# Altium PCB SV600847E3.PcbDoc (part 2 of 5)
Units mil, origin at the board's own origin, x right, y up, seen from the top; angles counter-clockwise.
Board outline 5404 x 2680 mil, 10 copper layers (Top Layer L1, Gnd-Plane - L2, Signals - L3, Gnd-Plane - L4, Pwr Plane - L5, Signals - L6, Gnd-Plane - L7, Signals - L8, Gnd-Plane - L9, Bottom Layer - L10), stack 57.8 mil thick; 517 components, 320 nets, 1784 pads, 1289 vias.
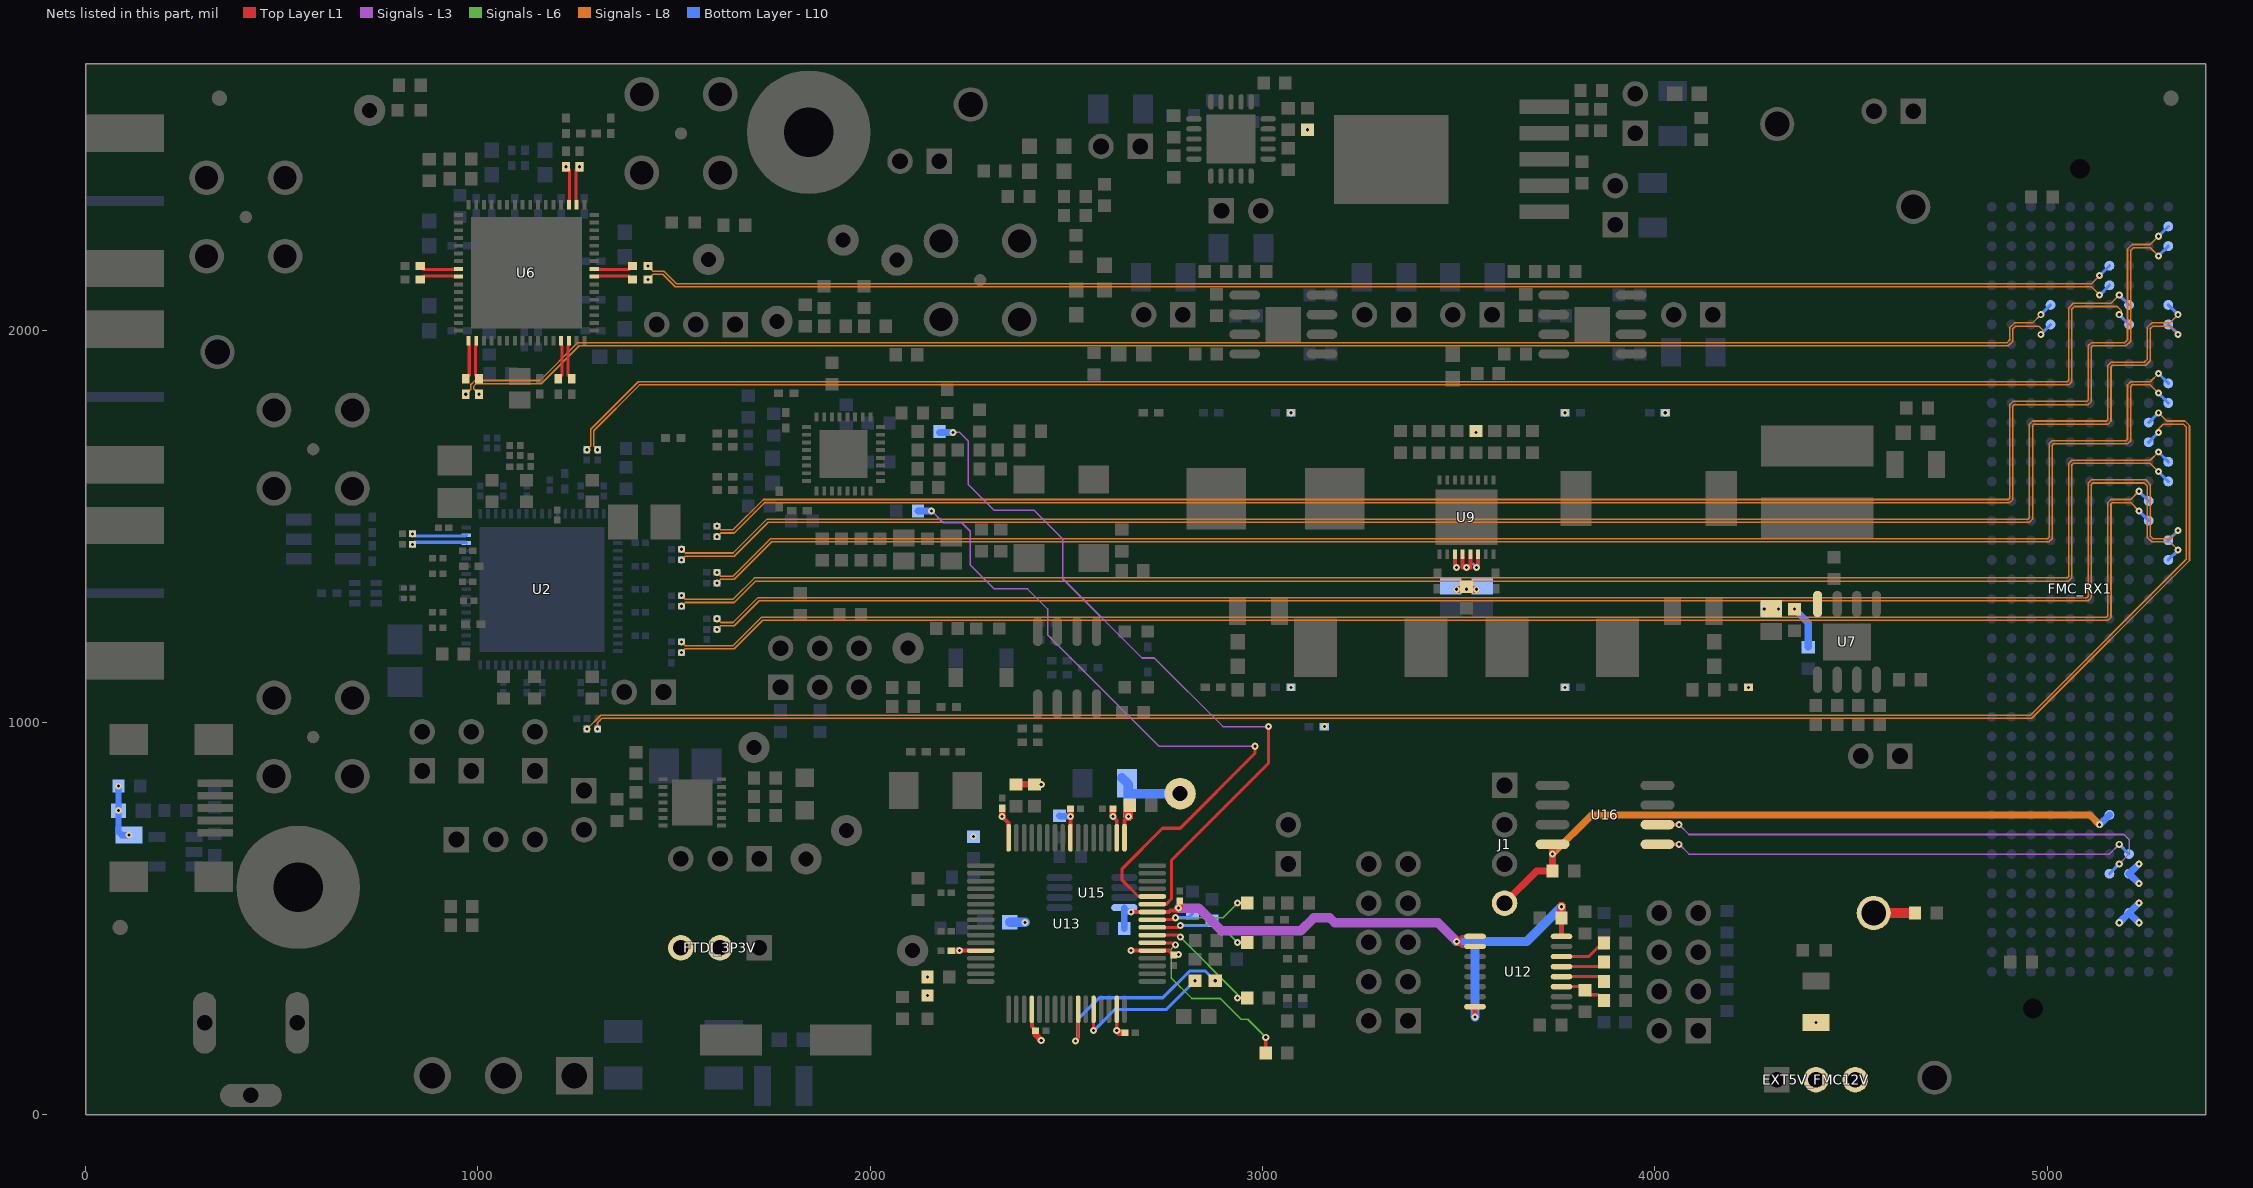
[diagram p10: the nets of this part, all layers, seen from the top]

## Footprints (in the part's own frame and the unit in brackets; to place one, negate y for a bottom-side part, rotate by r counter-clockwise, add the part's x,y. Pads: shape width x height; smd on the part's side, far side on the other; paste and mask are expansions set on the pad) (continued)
Keystone5011 [mil] "Keystone Multipurpose loops"
  round 87 hole 63: 1(0,0)
  silkscreen extent -70,-70 70,70, body extent -63,-63 63,62, height 319
Keystone_1902C [mil] "Hex Standoff, 4-40 threaded, nylon"
  round 1 on Mech4: 0(0,0)
  body extent -145,-126 146,126, height 501
Label_650x200 [mil] "Thermal Transfer Label"
  silkscreen extent -325,-100 325,100, body extent -326,-101 326,101, height 1
LED_LTST-C170 [mm] "LITE-ON"
  rect 1.2x1.2 smd: 1(-1.05,0) 2(1.05,0)
  silkscreen extent -1.6,-1.1 3,1.1, body extent -1.05,-0.67 1.05,0.67, height 1.1
LED_LTST-C190 [mm] "Lite-On"
  rect 0.8x0.8 smd: 1(-0.75,0) 2(0.75,0)
  silkscreen extent -1.1,-0.8 1.8,0.8, body extent -0.85,-0.45 0.85,0.45, height 0.9
LQFP64_N [mm] "Thin QFP, 64-Leads, Body 10x10mm, Pitch 0.5mm, IPC Medium Density"
  oval 1.8x0.3 smd mask+0.049: 1(-5.55,3.75) 2(-5.55,3.25) 3(-5.55,2.75) 4(-5.55,2.25) 5(-5.55,1.75) 6(-5.55,1.25) 7(-5.55,0.75) 8(-5.55,0.25) 9(-5.55,-0.25) 10(-5.55,-0.75) 11(-5.55,-1.25) 12(-5.55,-1.75) 13(-5.55,-2.25) 14(-5.55,-2.75) 15(-5.55,-3.25) 16(-5.55,-3.75) 33(5.55,-3.75) 34(5.55,-3.25) 35(5.55,-2.75) 36(5.55,-2.25) 37(5.55,-1.75) 38(5.55,-1.25) 39(5.55,-0.75) 40(5.55,-0.25) 41(5.55,0.25) 42(5.55,0.75) 43(5.55,1.25) 44(5.55,1.75) 45(5.55,2.25) 46(5.55,2.75) 47(5.55,3.25) 48(5.55,3.75)
  oval 0.3x1.8 smd mask+0.049: 17(-3.75,-5.55) 18(-3.25,-5.55) 19(-2.75,-5.55) 20(-2.25,-5.55) 21(-1.75,-5.55) 22(-1.25,-5.55) 23(-0.75,-5.55) 24(-0.25,-5.55) 25(0.25,-5.55) 26(0.75,-5.55) 27(1.25,-5.55) 28(1.75,-5.55) 29(2.25,-5.55) 30(2.75,-5.55) 31(3.25,-5.55) 32(3.75,-5.55) 49(3.75,5.55) 50(3.25,5.55) 51(2.75,5.55) 52(2.25,5.55) 53(1.75,5.55) 54(1.25,5.55) 55(0.75,5.55) 56(0.25,5.55) 57(-0.25,5.55) 58(-0.75,5.55) 59(-1.25,5.55) 60(-1.75,5.55) 61(-2.25,5.55) 62(-2.75,5.55) 63(-3.25,5.55) 64(-3.75,5.55)
  silkscreen extent -5.67,-4.25 4.25,4.57, body extent -5,-5 5,5, height 1.6
M08A_L [mm] "SOIC, 8-Leads, Body 4.9x3.9mm, Pitch 1.27mm, IPC High Density"
  oval 1.9x0.6 smd: 1(-2.35,1.905) 2(-2.35,0.635) 3(-2.35,-0.635) 4(-2.35,-1.905) 5(2.35,-1.905) 6(2.35,-0.635) 7(2.35,0.635) 8(2.35,1.905)
  silkscreen extent -2.47,-2.5 1,2.88, body extent -2,-2.5 2,2.5, height 1.75
Mini-Circuits-DB1627 [mm] "Mini-Circuits DB1627 Footprint"
  rect 0.76x1.65 smd: 1(-1.27,1.59) 2(0,1.59) 3(1.27,1.59) 4(1.27,-1.59) 5(0,-1.59) 6(-1.27,-1.59)
  silkscreen extent -3.01,-2.03 1.91,2.03, body extent -1.91,-2.03 1.91,2.03, height 4.07
MRA08A_N [mm] "SOIC, 8-Leads, Body 4.9x3.9mm, Pitch 1.27mm, Exposed Pad, IPC Medium Density"
  oval 2x0.6 smd: 1(-2.5,1.905) 2(-2.5,0.635) 3(-2.5,-0.635) 4(-2.5,-1.905) 5(2.5,-1.905) 6(2.5,-0.635) 7(2.5,0.635) 8(2.5,1.905)
  rect 2.29x2.29 smd: 9(0,0)
  silkscreen extent -2.63,-2.5 1.1,2.88, body extent -2,-2.5 2,2.5, height 1.68
MSOP-MS8_N [mm] "TSOP, 8-Leads, Body 3x3mm, Pitch 0.65mm, IPC Medium Density"
  oval 1.7x0.45 smd mask+0.049: 1(-2.1,0.975) 2(-2.1,0.325) 3(-2.1,-0.325) 4(-2.1,-0.975) 5(2.1,-0.975) 6(2.1,-0.325) 7(2.1,0.325) 8(2.1,0.975)
  silkscreen extent -2.22,-1.55 0.85,1.87, body extent -1.6,-1.6 1.6,1.6, height 1.1
MSS1038 [mil]
  rect 80x140 smd: 1(-185,0) 2(185,0)
  silkscreen extent -216,-208 215,208, body extent -203,-201 203,201, height 158
NKD0064A [mm] "QFN, 64-Leads, Body 9x9mm, Pitch 0.5mm"
  rect 0.6x0.25 smd mask+0.051: 1(-4.4,3.75) 2(-4.4,3.25) 3(-4.4,2.75) 4(-4.4,2.25) 5(-4.4,1.75) 6(-4.4,1.25) 7(-4.4,0.75) 8(-4.4,0.25) 9(-4.4,-0.25) 10(-4.4,-0.75) 11(-4.4,-1.25) 12(-4.4,-1.75) 13(-4.4,-2.25) 14(-4.4,-2.75) 15(-4.4,-3.25) 16(-4.4,-3.75) 33(4.4,-3.75) 34(4.4,-3.25) 35(4.4,-2.75) 36(4.4,-2.25) 37(4.4,-1.75) 38(4.4,-1.25) 39(4.4,-0.75) 40(4.4,-0.25) 41(4.4,0.25) 42(4.4,0.75) 43(4.4,1.25) 44(4.4,1.75) 45(4.4,2.25) 46(4.4,2.75) 47(4.4,3.25) 48(4.4,3.75)
  rect 0.25x0.6 smd mask+0.051: 17(-3.75,-4.4) 18(-3.25,-4.4) 19(-2.75,-4.4) 20(-2.25,-4.4) 21(-1.75,-4.4) 22(-1.25,-4.4) 23(-0.75,-4.4) 24(-0.25,-4.4) 25(0.25,-4.4) 26(0.75,-4.4) 27(1.25,-4.4) 28(1.75,-4.4) 29(2.25,-4.4) 30(2.75,-4.4) 31(3.25,-4.4) 32(3.75,-4.4) 49(3.75,4.4) 50(3.25,4.4) 51(2.75,4.4) 52(2.25,4.4) 53(1.75,4.4) 54(1.25,4.4) 55(0.75,4.4) 56(0.25,4.4) 57(-0.25,4.4) 58(-0.75,4.4) 59(-1.25,4.4) 60(-1.75,4.4) 61(-2.25,4.4) 62(-2.75,4.4) 63(-3.25,4.4) 64(-3.75,4.4)
  rect 7.2x7.2 smd paste-3.6 mask+0.051: 65(0,0)
  silkscreen extent -5.52,-4.85 4.85,4.85, body extent -4.55,-4.55 4.55,4.55, height 0.8
"NY PMS 440 0025 PH"#1 [mm] "4-40 nylon screw and mounting hole"
  round 8 / inner round 4.216 / far side round 8 hole 3.2 mask+0.037: 1(0,0)
  body extent -3.3,-3.3 3.3,3.3, height 2.69
"NY PMS 440 0025 PH"#2 [mm] "4-40 nylon screw and mounting hole"
  round 8 / inner round 4.216 / far side round 8 hole 3.2: 1(0,0)
  body extent -3.3,-3.3 3.3,3.3, height 2.69
OSC_CWX [mm] "CONNOR WINFIELD"
  rect 2x1.8 smd: 1(-2.1,2.54) 2(-2.1,-2.54) 3(2.1,-2.54) 4(2.1,2.54)
  silkscreen extent -2.7,-3.7 2.7,4.55, body extent -2.65,-3.65 2.65,3.65, height 1.31
PBC03SAAN [mm] "Sullins 100mil, 1x3, 230 mil above insulator"
  rect 1.65x1.65 hole 1.016: 1(-2.54,0)
  round 1.65 hole 1.016: 2(0,0) 3(2.54,0)
  silkscreen extent -3.81,-1.27 3.81,1.27, body extent -3.81,-1.27 3.81,1.27, height 8.38
PW0016A_L [mm] "TSOP, 16-Leads, Body 5x4.4mm, Pitch 0.65mm, IPC High Density"
  oval 1.4x0.35 smd: 1(-2.8,2.275) 2(-2.8,1.625) 3(-2.8,0.975) 4(-2.8,0.325) 5(-2.8,-0.325) 6(-2.8,-0.975) 7(-2.8,-1.625) 8(-2.8,-2.275) 9(2.8,-2.275) 10(2.8,-1.625) 11(2.8,-0.975) 12(2.8,-0.325) 13(2.8,0.325) 14(2.8,0.975) 15(2.8,1.625) 16(2.8,2.275)
  silkscreen extent -2.92,-2.55 1.7,3.12, body extent -2.25,-2.55 2.25,2.55, height 1.2
RGW0020A [mm] "QFN, 20-Leads, Body 5x5mm, Pitch 0.65mm, Thermal Pad 3.15x3.15mm, TI Recommended"
  oval 1x0.35 smd paste-0.025 mask+0.07: 1(-2.4,1.3) 2(-2.4,0.65) 3(-2.4,0) 4(-2.4,-0.65) 5(-2.4,-1.3) 11(2.4,-1.3) 12(2.4,-0.65) 13(2.4,0) 14(2.4,0.65) 15(2.4,1.3)
  oval 0.35x1 smd paste-0.025 mask+0.07: 6(-1.3,-2.4) 7(-0.65,-2.4) 8(0,-2.4) 9(0.65,-2.4) 10(1.3,-2.4) 16(1.3,2.4) 17(0.65,2.4) 18(0,2.4) 19(-0.65,2.4) 20(-1.3,2.4)
  rect 3.15x3.15 smd paste-1.575 mask+0.07: 21(0,0)
  silkscreen extent -3.5,-2.73 2.73,2.73, body extent -2.58,-2.57 2.57,2.58, height 1
RLY0068A [mm] "QFN, 68-Leads, Body 10x10mm, Pitch 0.5mm"
  rect 0.6x0.25 smd mask+0.051: 1(-4.9,4) 2(-4.9,3.5) 3(-4.9,3) 4(-4.9,2.5) 5(-4.9,2) 6(-4.9,1.5) 7(-4.9,1) 8(-4.9,0.5) 9(-4.9,0) 10(-4.9,-0.5) 11(-4.9,-1) 12(-4.9,-1.5) 13(-4.9,-2) 14(-4.9,-2.5) 15(-4.9,-3) 16(-4.9,-3.5) 17(-4.9,-4) 35(4.9,-4) 36(4.9,-3.5) 37(4.9,-3) 38(4.9,-2.5) 39(4.9,-2) 40(4.9,-1.5) 41(4.9,-1) 42(4.9,-0.5) 43(4.9,0) 44(4.9,0.5) 45(4.9,1) 46(4.9,1.5) 47(4.9,2) 48(4.9,2.5) 49(4.9,3) 50(4.9,3.5) 51(4.9,4)
  rect 0.25x0.6 smd mask+0.051: 18(-4,-4.9) 19(-3.5,-4.9) 20(-3,-4.9) 21(-2.5,-4.9) 22(-2,-4.9) 23(-1.5,-4.9) 24(-1,-4.9) 25(-0.5,-4.9) 26(0,-4.9) 27(0.5,-4.9) 28(1,-4.9) 29(1.5,-4.9) 30(2,-4.9) 31(2.5,-4.9) 32(3,-4.9) 33(3.5,-4.9) 34(4,-4.9) 52(4,4.9) 53(3.5,4.9) 54(3,4.9) 55(2.5,4.9) 56(2,4.9) 57(1.5,4.9) 58(1,4.9) 59(0.5,4.9) 60(0,4.9) 61(-0.5,4.9) 62(-1,4.9) 63(-1.5,4.9) 64(-2,4.9) 65(-2.5,4.9) 66(-3,4.9) 67(-3.5,4.9) 68(-4,4.9)
  rect 8.1x8.1 smd paste-4.05 mask+0.051: 69(0,0)
  silkscreen extent -5.87,-5.2 5.2,5.2, body extent -5.05,-5.05 5.05,5.05, height 1.01
RTV0032A [mm] "QFN, 32-Leads, Body 5x5mm, Pitch 0.5mm"
  rect 0.6x0.25 smd mask+0.051: 1(-2.4,1.75) 2(-2.4,1.25) 3(-2.4,0.75) 4(-2.4,0.25) 5(-2.4,-0.25) 6(-2.4,-0.75) 7(-2.4,-1.25) 8(-2.4,-1.75) 17(2.4,-1.75) 18(2.4,-1.25) 19(2.4,-0.75) 20(2.4,-0.25) 21(2.4,0.25) 22(2.4,0.75) 23(2.4,1.25) 24(2.4,1.75)
  rect 0.25x0.6 smd mask+0.051: 9(-1.75,-2.4) 10(-1.25,-2.4) 11(-0.75,-2.4) 12(-0.25,-2.4) 13(0.25,-2.4) 14(0.75,-2.4) 15(1.25,-2.4) 16(1.75,-2.4) 25(1.75,2.4) 26(1.25,2.4) 27(0.75,2.4) 28(0.25,2.4) 29(-0.25,2.4) 30(-0.75,2.4) 31(-1.25,2.4) 32(-1.75,2.4)
  rect 3.1x3.1 smd paste-1.55 mask+0.051: 33(0,0)
  silkscreen extent -3.52,-2.85 2.85,2.85, body extent -2.55,-2.55 2.55,2.55, height 0.8
SDA14B [mm] "SON, 14-Leads, Body 4x4mm, Pitch 0.5mm, NSC Recommended"
  rect 0.6x0.25 smd paste-0.125 mask+0.051: 1(-1.9,1.5) 2(-1.9,1) 3(-1.9,0.5) 4(-1.9,0) 5(-1.9,-0.5) 6(-1.9,-1) 7(-1.9,-1.5) 8(1.9,-1.5) 9(1.9,-1) 10(1.9,-0.5) 11(1.9,0) 12(1.9,0.5) 13(1.9,1) 14(1.9,1.5)
  rect 2.6x3 smd paste-1.3 mask+0.051: 15(0,0)
  silkscreen extent -2.82,-2.2 2.35,2.87, body extent -2.05,-2.05 2.05,2.05, height 0.8
SDA16A [mm] "SON, 16-Leads, Body 5x5mm, Pitch 0.5mm, NSC Recommended"
  rect 0.6x0.25 smd paste-0.125 mask+0.051: 1(-2.4,1.75) 2(-2.4,1.25) 3(-2.4,0.75) 4(-2.4,0.25) 5(-2.4,-0.25) 6(-2.4,-0.75) 7(-2.4,-1.25) 8(-2.4,-1.75) 9(2.4,-1.75) 10(2.4,-1.25) 11(2.4,-0.75) 12(2.4,-0.25) 13(2.4,0.25) 14(2.4,0.75) 15(2.4,1.25) 16(2.4,1.75)
  rect 3.6x4 smd paste-1.8 mask+0.051: 17(0,0)
  silkscreen extent -2.85,-2.7 2.85,3.53, body extent -2.55,-2.55 2.55,2.55, height 0.8
SM_RADIAL_F [mm] "8 x 10.2mm:  Panasonic F"
  rect 4x2 smd: 1(-3.55,0) 2(3.55,0)
  silkscreen extent -4.25,-4.25 4.25,4.25, body extent -4.26,-4.26 4.26,4.26, height 10.5
SMC [mil] "Molded Diode, 2-Leads, Body 6.9x5.8mm, IPC Medium Density, based on OnSemi component dimensions and land patterns"
  rect 110x150 smd: 1(-140.49,0) 2(140.49,0)
  silkscreen extent -221,-124 189,124, body extent -156,-116 156,116, height 91
SNT-100-BK-G [mil] "Samtec STEP model"
  round 1 on Mech3: 0(0,0)
  body extent -100,-50 100,50, height 344
SOD-123 [mm] "On Semi recommended land pattern"
  rect 0.915x1.22 smd: 1(-1.637,0) 2(1.637,0)
  silkscreen extent -2.74,-1.17 2.03,1.17, body extent -1.93,-0.9 1.93,0.9, height 1.35
SOIJ-SM8_N [mm] "SOP, 8-Leads, Body 5.2x5.2mm, Pitch 1.27mm, IPC Medium Density"
  oval 2.2x0.6 smd: 1(-3.4,1.905) 2(-3.4,0.635) 3(-3.4,-0.635) 4(-3.4,-1.905) 5(3.4,-1.905) 6(3.4,-0.635) 7(3.4,0.635) 8(3.4,1.905)
  silkscreen extent -3.52,-2.75 1.9,2.88, body extent -2.73,-2.75 2.73,2.75, height 2.04
"SW_ L101011MS02Q" [mm] "SWITCH SLIDE sPST 4A PCB"
  rect 2.416x2.416 hole 1.65: 1(2.855,4.6)
  round 2.416 hole 1.65: 2(2.855,0) 3(2.855,-4.6)
  silkscreen extent -5.4,-9.55 5.4,9.55, body extent -5.39,-9.55 5.39,9.55, height 14.18
TESTPOINT [mil]
  round 80 hole 37.99: 1(0,0)
TI_Symbol_Overlay_Small [mil]
  silkscreen extent -90,-88 91,88
TJ5A_N [mm] "D2-PAK, 6-Leads, Body 9.9x10.2mm, Pitch 1.7mm, Lead Span 14mm, IPC Medium Density"
  rect 3.2x0.95 smd: 1(-6,3.4) 2(-6,1.7) 3(-6,0) 4(-6,-1.7) 5(-6,-3.4)
  rect 7.4x5.75 smd: 6(3.9,0)
  silkscreen extent -6.12,-5.2 -0.2,5.2, body extent -1.95,-5.2 8.15,5.2, height 2.1
TSW-102-07-G-S [mm] "Samtec 100mil, 1x2, 230 mil above insulator"
  rect 1.65x1.65 hole 1.016 mask+0: 1(-1.27,0)
  round 1.65 hole 1.016 mask+0: 2(1.27,0)
  silkscreen extent -3.56,-1.27 2.54,1.27, body extent -2.54,-1.27 2.54,1.27, height 8.38
TSW-103-07-G-D [mm] "Samtec 100mil, 2x3, 230 mil above insulator"
  rect 1.65x1.65 hole 1.016 mask+0: 1(-2.54,-1.27)
  round 1.65 hole 1.016 mask+0: 2(-2.54,1.27) 3(0,-1.27) 4(0,1.27) 5(2.54,-1.27) 6(2.54,1.27)
  silkscreen extent -4.83,-2.54 3.81,2.54, body extent -3.81,-2.54 3.81,2.54, height 8.38
TSW-103-07-G-S [mm] "Samtec 100mil, 1x3, 230 mil above insulator"
  rect 1.65x1.65 hole 1.016 mask+0: 1(-2.54,0)
  round 1.65 hole 1.016 mask+0: 2(0,0) 3(2.54,0)
  silkscreen extent -4.84,-1.27 3.81,1.27, body extent -3.81,-1.27 3.81,1.27, height 8.38
TSW-104-07-G-D [mm] "Samtec 100mil, 2x4, 230 mil above insulator"
  rect 1.65x1.65 hole 1.016 mask+0: 1(-3.81,-1.27)
  round 1.65 hole 1.016 mask+0: 2(-3.81,1.27) 3(-1.27,-1.27) 4(-1.27,1.27) 5(1.27,-1.27) 6(1.27,1.27) 7(3.81,-1.27) 8(3.81,1.27)
  silkscreen extent -6.1,-2.54 5.08,2.54, body extent -5.08,-2.54 5.08,2.54, height 8.38
TSW-104-07-G-S [mm] "Samtec 100mil, 1x4, 230 mil above insulator"
  rect 1.65x1.65 hole 1.016 mask+0: 1(-3.81,0)
  round 1.65 hole 1.016 mask+0: 2(-1.27,0) 3(1.27,0) 4(3.81,0)
  silkscreen extent -6.1,-1.27 5.08,1.27, body extent -5.08,-1.27 5.08,1.27, height 8.38
WE-HC6 [mm] "Wurth Electronik recommended land pattern"
  rect 3.85x4 smd: 1(-3.825,0) 2(3.825,0)
  silkscreen extent -6.2,-6.2 6.2,6.2, body extent -5.77,-5.37 5.75,5.35, height 5
XTAL_ABM3 [mm] "Abracon recommended land pattern 12.28.10"
  rect 1.9x2.4 smd: 1(-2.05,0) 2(2.05,0)
  silkscreen extent -2.67,-1.78 2.67,1.78, body extent -2.6,-1.7 2.6,1.7, height 1.3

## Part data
1P8USB 3P3USB FLout LD1 LD2 MUX TCRIT1 TCRIT2 TCRIT3 TP_LD Vtune: "TEST POINT.  No entry in BOM."
1V2ADC_INT 1V2ADC_LDO 1V9ADC 1V9INT J3 "KC705 JTAG" LMK_INT LMK_LDO LMX_INT LMX_LDO PG_RX1 Tdiode VA12 VA19 Vbg Vcmo VD12: "Header, TH, 100mil, 2x1, Gold plated, 230 mil above insulator"
3P3RX GND GND1 GND2 GND3 VADJ_RX: "Test Point, TH, Multipurpose, Black"
5VDC: "Connector, DC Jack 2.1X5.5 mm, TH"
12V LD MUXout Status1 Status2 USB_PWR: "LED, Green, SMD"
C1 C3 C5 C6: "CAP, CERM, 100pF, 16V, +/-10%, X7R, 0201"
C2 C8 C11 C215 C216 C217 C218 C219 C220 C221 C222 C223 C224 C225 C226 C227: "CAP, CERM, 0.1uF, 10V, +/-10%, X7R, 0402"
C4: "CAP, CERM, 10pF, 50V, +/-5%, C0G/NP0, 0402"
C7 C9 C10 C12 C13 C14 C15 C17 C20 C21 C22 C23 C26 C28 C29 C31 C41 C42 C43 C44 C45 C46 C47 C51 C52 C53 C54 C55 C56 C57 C58 C62 C63 C64 C65 C66 C67 C68 C69 C70 C71 C118 C119 C131 C132 C133 C134 C136 C140 C142 C214: library part Capacitor, "CAP, CERM, 0.1uF, 6.3V, X5R, 10%, 0201"
C16: "CAP, CERM, 4.7uF, 6.3V, +/-20%, X5R, 0402"
C18 C19 C103 C104 C105 C106 C107 C109 C110 C111 C112 C113 C114 C120 C121 C123 C124 C206 C207 C208 C209: "CAP, CERM, 0.1uF, 10V, +/-10%, X5R, 0402"
C24 C74 C79 C115 C210: "CAP, CERM, 0.1uF, 16V, +/-5%, X7R, 0603"
C25 C34 C38 C76 C77 C78 C88 C89 C91 C93 C94 C98 C99: "CAP, CERM, 100pF, 50V, +/-5%, C0G/NP0, 0603"
C27 C48 C59 C72: "CAP, TANT, 10uF, 10V, +/-20%, 2.5 ohm, 3528-21 SMD"
C30 C36: "CAP, CERM, 0.22uF, 6.3V, +/-20%, X5R, 0201"
C32 C33 C35 C37: "CAP, CERM, 4700pF, 10V, +/-10%, X5R, 0201"
C39 C40 C49 C50 C60 C61 C125 C143 C205: "CAP, CERM, 1uF, 10V, +/-10%, X5R, 0603"
C73: "CAP, CERM, 1uF, 16V, +/-10%, X7R, 0603"
C75 C95 C96 C97 C100 C101 C213: "CAP, CERM, 100pF, 25V, +/-5%, C0G/NP0, 0402"
C80 C82 C139 C141 C150 C152 C158 C163 C165 C166 C171 C172 C186 C188 C190 C195 C196 C197 C200 C202 C203 C204: "CAP, CERM, 10uF, 10V, +/-10%, C0G/NP0, 0603"
C81 C83: "CAP, CERM, 22uF, 10V, +/-20%, X5R, 0805"
C84: "CAP, CERM, 2.2uF, 10V, +/-10%, X5R, 0603"
C85: "CAP, CERM, 0.01uF, 100V, +/-10%, X7R, 0603"
C86: "CAP, CERM, 1500pF, 50V, +/-5%, C0G/NP0, 0603"
C87: "CAP, CERM, 0.1uF, 50V, +/-10%, X7R, 0603"
C90: "CAP, CERM, 0.022uF, 25V, +/-10%, X7R, 0603"
C92: "CAP, CERM, 680pF, 100V, +/-5%, X7R, 0603"
C102: "CAP, CERM, 0.01uF, 16V, +/-10%, X7R, 0402"
C108 C155 C201 C211: "CAP, CERM, 1uF, 16V, +/-10%, X5R, 0603"
C116 C126 C129 C130 C144 C147 C148 C151 C153 C159 C164 C167 C176 C177 C185 C189 C191 C198 C199: "CAP, CERM, 0.1uF, 25V, +/-5%, X7R, 0603"
C117 C149: "CAP, CERM, 330pF, 50V, +/-5%, C0G/NP0, 0603"
C122: "CAP, CERM, 10uF, 10V, +/-10%, X5R, 0805"
C127 C160: "CAP, CERM, 4.7uF, 10V, +/-10%, X5R, 0603"
C128 C161: "CAP, CERM, 0.01uF, 100V, +/-20%, X7R, 0603"
C135 C137: "CAP, CERM, 18pF, 50V, +/-5%, C0G/NP0, 0402"
C138 C212: "CAP, CERM, 100uF, 6.3V, +/-20%, X5R, 1206"
C145 C146 C173 C184: "CAP, CERM, 10uF, 16V, +/-10%, X5R, 0805"
C154: "CAP, CERM, 10pF, 50V, +/-5%, C0G/NP0, 0603"
C156 C157: "CAP, CERM, 47uF, 6.3V, +/-20%, X5R, 1206"
C162: "CAP, CERM, 3300pF, 25V, +/-10%, X7R, 0603"
C168: "CAP, CERM, 0.22uF, 16V, +/-10%, X7R, 0603"
C169 C170: "CAP, CERM, 0.1uF, 6.3V, +/-10%, X5R, 0402"
C174 C175: "CAP, CERM, 0.027uF, 16V, +/-10%, X7R, 0603"
C178 C179: "CAP, CERM, 0.039uF, 25V, +/-10%, X7R, 0603"
C180 C181 C182 C183: "CAP, CERM, 22uF, 10V, +/-20%, X5R, 1206"
C187: "CAP, CERM, 560pF, 50V, +/-5%, C0G/NP0, 0603"
C192: "CAP, CERM, 4700pF, 16V, +/-10%, X7R, 0603"
C193: "CAP, AL, 100uF, 25V, +/-20%, 0.3 ohm, SMD"
C194: "CAP, CERM, 10uF, 25V, +/-10%, X6S, 1210"
C228 C229: library part GRM155R71A104KA01D, "CAP CER 0.5PF 50V NP0 0402"
D2 D4: "Diode, Ultrafast, 100V, 0.15A, SOD-123"
D11 D12: "Diode, Schottky, 40V, 5A, SMC"
DEVCLK LMKCLK OSCin VIN+ VIN-: "Connector, SMA,Vertical, Thru hole w/SMT center pin"
EXT5V_FMC12V: "Header, TH, 100mil, 1x3, Gold plated, 230 mil above insulator"
FID1 FID2 FID3: "Fiducial mark.  There is nothing to buy or mount."
FMC_RX1: "Connector, Receptacle, 400-Pos (40x10), 50x50-mil Pitch, SMT"
FTDI_3P3V OR RSV "Ts ADD1": "Header, TH, 100mil, 3x1, Gold plated, 230 mil above insulator"
H3 H4: library part 1902C, "Standoff, Hex, 0.25\"L #4-40 Nylon"
H5 H6: "Machine Screw, Round, #4-40 x 1/4, Nylon, Philips panhead"
J1: "Header, TH, 100mil, 4x1, Gold plated, 230 mil above insulator"
L1 L7 L14 L20 L24 L25: "3A Ferrite Bead, 120 ohm @ 100MHz, SMD"
L2 L3 L4 L5 L19 L21 L22 L23: "1.5A Ferrite Bead, 330 ohm @ 100MHz, SMD"
L6 L9 L10 L13 L15 L16 L17 L18 L26: "6A Ferrite Bead, 26 ohm @ 100MHz, SMD"
L8: "Inductor, Shielded Drum Core, Ferrite, 3uH, 3A, 0.024 ohm, SMD"
L11: "Inductor, Shielded Drum Core, Ferrite, 7uH, 4.35A, 0.03 ohm, SMD"
L12: "Inductor, Shielded Drum Core, Superflux, 5.5uH, 10A, 0.0112 ohm, SMD"
LBL1: library part THT-14-423-10, "Thermal Transfer Printable Labels, 0.650\" W x 0.200\" H - 10,000 per roll"
LF1: "CAP, CERM, 3900pF, 25V, +/-5%, C0G/NP0, 0603"
LF2: "CAP, CERM, 47pF, 50V, +/-5%, C0G/NP0, 0603"
LF3: "RES, 619 ohm, 1%, 0.1W, 0603"
LF7: "Coupled inductor, 5A, 0.01 ohm, SMD"
Logo1: library part ESD_Susceptible, "ESD Susceptible Symbol"
Logo2: library part TI_Logo, "Texas Instrument Corporate Signature"
NCO: "Header, TH, 100mil, 3x2, Gold plated, 230 mil above insulator"
OR_T0 OR_T1: "LED, Orange, SMD"
R1: "RES, 8.06k ohm, 1%, 0.063W, 0402"
R2 R10: "RES, 1.2k ohm, 5%, 0.063W, 0402"
R3 R11: "RES, 1.0Meg ohm, 5%, 0.063W, 0402"
R4 R5 R6 R14 R15 R16 R105 R106 R107 R123 R130 R131: "RES, 10.0k ohm, 1%, 0.1W, 0603"
R7 R8 R9 R18 R19 R20 R21 R22 R23: library part "Res 0201 placeholder", "RES 0.0 OHM 1/20W 0201 SMD"
R12: "RES, 1.33k ohm, 1%, 0.063W, 0402"
R13: "RES, 3.30k ohm, 0.1%, 0.1W, 0603"
R17: "RES, 750 ohm, 5%, 0.1W, 0603"
R24 R30 R103 R132 R142 R143 RR7: "RES, 0 ohm, 5%, 0.1W, 0603"
R25 R29: "RES, 18 ohm, 5%, 0.1W, 0603"
R26: "RES, 9.09k ohm, 1%, 0.1W, 0603"
R27: "RES, 56 ohm, 5%, 0.1W, 0603"
R28: "RES, 68 ohm, 5%, 0.1W, 0603"
R31 R32 R46 R117 R122: "RES, 1.3k ohm, 5%, 0.1W, 0603"
R33 R34: "RES, 430 ohm, 1%, 0.1W, 0603"
R35 R36 R37 R38 R51: "RES, 51 ohm, 5%, 0.063W, 0402"
R39 R71 R80 R134: "RES, 1.0k ohm, 5%, 0.1W, 0603"
R40 R42 R73 R75 R83 R84 R92 R95: "RES, 0.002 ohm, 1%, 1W, 1206"
R41 R74: "RES, 10.7k ohm, 1%, 0.1W, 0603"
R43 R44 R48 R59 R60 R61 R62 R63 R64: "RES, 0 ohm, 5%, 0.063W, 0402"
R45 R56 R99 R100 R112: "RES, 270 ohm, 5%, 0.1W, 0603"
R47: "RES, 2.32k ohm, 1%, 0.1W, 0603"
R49 R77: "RES, 4.64k ohm, 1%, 0.1W, 0603"
R50: library part "Res 0402 placeholder_1", "Generic symbol for 0402 Res placeholder"
R52 R53: "RES, 10 ohm, 5%, 0.1W, 0603"
R54 R55 R57 R58 R65 R68 R69 R109 R110 R111 R113 R114 R115 R118 R119 R120 R121 R124 R125 R126 R127: "RES, 100 ohm, 5%, 0.1W, 0603"
R66 R93 R133: "RES, 1.00k ohm, 1%, 0.1W, 0603"
R67: "RES, 12.0k ohm, 1%, 0.1W, 0603"
R70: "RES, 10k ohm, 5%, 0.1W, 0603"
R72: "RES, 82.5k ohm, 1%, 0.1W, 0603"
R76: "RES, 22.1k ohm, 1%, 0.1W, 0603"
R78: "RES, 10.0 ohm, 1%, 0.1W, 0603"
R79: "RES, 732 ohm, 1%, 0.1W, 0603"
R81: "RES, 16.2k ohm, 1%, 0.1W, 0603"
R82: "RES, 7.87k ohm, 1%, 0.1W, 0603"
R85: "RES, 2.49k ohm, 1%, 0.1W, 0603"
R86 R87: "RES, 5.90k ohm, 1%, 0.1W, 0603"
R88 RR6: "RES, 4.99k ohm, 1%, 0.1W, 0603"
R89: "RES, 2.80k ohm, 1%, 0.1W, 0603"
R90: "RES, 402 ohm, 1%, 0.1W, 0603"
R94: "RES, 1.0k ohm, 5%, 0.25W, 1206"
R96: "RES, 357 ohm, 1%, 0.1W, 0603"
R97 R98 R101 R102: "RES, 12.4k ohm, 1%, 0.1W, 0603"
R104 R116 R128 R129: "RES, 24k ohm, 5%, 0.063W, 0402"
R108: "RES, 2.2k ohm, 5%, 0.1W, 0603"
R135: "RES, 2.10k ohm, 1%, 0.1W, 0603"
R136 R137 R138: "RES, 4.7k ohm, 5%, 0.1W, 0603"
R139 R140 R141: "RES, 2.0k ohm, 5%, 0.1W, 0603"
S1: "SWITCH SLIDE SPST 4A PCB, TH"
SH-1V2ADC_INT_1_2 SH-1V2ADC_LDO_1_2 SH-1V9ADC_1_2 SH-1V9INT_1_2 SH-5V_12V_1_2 SH-FTDI_3P3V_1_2 SH-LMK_INT_1_2 SH-LMK_LDO_1_2 SH-LMX_INT_1_2 SH-LMX_LDO_1_2 SH-RSV_1_2 "SH-Ts ADD1_1_2": "Shunt, 100mil, Gold plated, Black"
SPI: "Header, TH, 100mil, 4x2, Gold plated, 230 mil above insulator"
T1: "Transformer, Multi-layer balun"
T2: "Transformer, RF, 50 ohm, 10 to 4000 MHz, SMT"
TEMP: "LED, Red, SMD"
TMST+ TMST- VIN: "Connector, SMT, End launch SMA 50 ohm"
U1: "Dual Micro-Power Rail-to-Rail Input CMOS Comparator with Push-Pull Output, 8-pin Narrow SOIC"
U2: library part ADC12X3500RFLQNOPB, "ADC12J4000RLY Ultra-Wideband RF Sampling Subsystem, RLY0068A"
U3: "Dual Remote Diode and Local Temperature Sensor with SMBus Interface and TruTherm Technology, 14-pin LLP, Pb-Free"
U4: "LMX2581 Wideband Frequency Synthesizer with Integrated VCO, RTV0032A"
U5 U8: "Micropower 800mA Low Noise \"Ceramic Stable\" Adjustable Voltage Regulator for 1V to 5V Applications, 8-pin PSOP, Pb-Free"
U6: "Low-Noise Clock Jitter Cleaner with Dual Loop PLLs, NKD0064A"
U7: "3-A OUTPUT SINGLE SYNCRONOUS STEP DOWN SWITCHER WITH INTEGRATED FET(SWIFT), DDA0008B"
U9: "Dual 2A, 500kHz Wide Input Range Buck Regulator, 16-pin LLP, Pb-Free"
U10: "3.0A Low Dropout Linear Regulator with Programmable Soft-Start, RGW0020A"
U11: "3A Fast-Transient Response Adjustable Low-Dropout Linear Voltage Regulator, 5-pin TO-263 Thin, Pb-Free"
U12: "4-BIT DUAL-SUPPLY BUS TRANSCEIVER WITH CONFIGURABLE VOLTAGE TRANSLATION AND 3-STATE OUTPUTS, PW0016A"
U13: "Quad High Speed USB to Multipurpose UART/MPSSE IC"
U14: "300-mA, Low-IQ, Low-Dropout Regulator, DBV0005A"
U15: "1K, 64x16-bit, 2.5V Microwire Serial EEPROM, 8-Pin MSOP, Industrial Temperature"
U16: "64Kbit, 400kHz, 4.5V, I2C Serial EEPROM, 8-Pin SOIC 208mil, Commercial Temperature, Tape and Reel"
USB: "MINI USB 2.0 SMT TYPE AB 5 CONTACTS R/A, SMD"
uWIRE: "Connector, 100mil Shrouded, 5x2, High-Temperature, Gold, TH"
Y1: "OSC 100.0000MHZ 3.3V +-25PPM SMD"
Y2: "Crystal, 12Mhz, 18pF, SMD"
ZZ1: library part AssemblyNoteLabel
ZZ2 ZZ3 ZZ4: library part AssemblyNote

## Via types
v1: diameter 18, hole 8, Top Layer L1 to Bottom Layer - L10, tented both sides, 1069 vias
v2: diameter 19.68, hole 7.87, Top Layer L1 to Bottom Layer - L10, 95 vias
v3: diameter 18, hole 8, Top Layer L1 to Bottom Layer - L10, tented bottom, 56 vias
v4: diameter 18, hole 8, Top Layer L1 to Bottom Layer - L10, tented top, 54 vias
v5: diameter 25.98, hole 12.99, Top Layer L1 to Bottom Layer - L10, tented top, 8 vias
v6: diameter 19.68, hole 7.87, Top Layer L1 to Bottom Layer - L10, tented top, 5 vias
v7: diameter 126, hole 106, Top Layer L1 to Bottom Layer - L10, tented top, 2 vias

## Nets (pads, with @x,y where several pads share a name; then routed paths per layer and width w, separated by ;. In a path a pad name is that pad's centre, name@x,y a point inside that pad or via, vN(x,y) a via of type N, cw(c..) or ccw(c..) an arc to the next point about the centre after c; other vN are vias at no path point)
1P8V_USB: 1P8USB.1 C133.1 C134.1 C136.1 C200.1 C212.2 U13.12 U13.37 U13.49 U13.64 | length 608
  Top Layer L1 w10: v1(2227.5,419.1) U13.12@2281.97,419.1 ; v1(2336,760.97) 2352.83,744.14 U13.64@2352.83,706.5 ; U13.49@2648.11,706.5 2648.11,751.13 v1(2657.95,760.97) ; v1(2664.51,419.1) U13.37@2718.98,419.1 2761.83,419.1 C134.1@2773.45,407.49 2775.22,409.26 v1(2786,409.26)
  Top Layer L1 w16.5: C133.1@2206.44,419.1 v1(2227.5,419.1) ; v1(2336,760.97) C136.1@2336,782.03
  Top Layer L1 w24: v1(2657.95,760.97) 2657.95,785.96 C200.1@2661.7,789.7
  Bottom Layer - L10 w24: C212.2@2641,860.09 C212.2@2655.09,846 ; v1(2657.95,760.97) C212.2@2657.95,843.13 ; C212.2@2657.95,819 1P8USB.1@2790,819
3P3V_FTDI: C118.1 C119.1 C129.1 C131.1 C132.1 C205.1 C214.1 FTDI_3P3V.2 L24.1 L25.1 R66.2 R105.2 R106.2 R107.2 U12.1 U12.2 U12.8 U12.16 U13.20 U13.31 U13.42 U13.50 U13.56 U15.8 USB_PWR.1 | length 2142.6
  Top Layer L1 w8: U12.2@3541.76,429.5 3507.79,429.5 v1(3495,442.3) 3507.8,455.1 U12.1@3541.76,455.1
  Top Layer L1 w10: U13.20@2411.89,269.5 2411.89,224.87 C118.1@2421.73,215.03 ; U13.56@2510.31,706.5 v1(2510.31,760.97) ; v1(2618.58,760.97) 2628.42,751.13 U13.50@2628.42,706.5 ; v1(2628.43,215.03) U13.31@2628.42,269.5 ; v1(2664.51,517.53) U13.42@2718.98,517.53 2761.83,517.53 2765.14,520.84 2779.47,520.84 v1(2786,527.37)
  Top Layer L1 w13: v1(3541.76,250) U12.8@3541.76,275.96 ; U12.16@3762.24,455.1 C129.1@3762.24,502.06
  Top Layer L1 w16: v1(2786,527.37) 2789.45,530.82 C131.1@2789.45,545.43
  Top Layer L1 w16.5: R107.2@2371.2,842.56 v1(2436,842.56) ; C118.1@2421.73,215.03 2421.73,204.27 v1(2436,190) ; v1(2510.31,760.97) C132.1@2510.31,781.24 ; v1(2618.58,760.97) C214.1@2618.58,781.24 ; v1(2628.43,215.03) 2633.43,210.03 C119.1@2649.48,210.03
  Top Layer L1 w24: C129.1@3762.24,502.06 v1(3762.24,530.79)
  Signals - L3 w24: v1(2786,527.37) 2837.63,527.37 2895,470 3098,470 3131,503 3171,503 3184,490 3447.3,490 v1(3495,442.3)
  Bottom Layer - L10 w16.5: R105.2@2482.32,762.56 2483.91,760.97 v1(2510.31,760.97) ; C205.1@2647.68,475 U15.8@2647.68,528.61 ; 2647.68,517.53 v1(2664.51,517.53)
  Bottom Layer - L10 w24: L24.1@2355.5,491 v1(2395,491) ; v1(3495,442.3) 3541.76,442.3 ; v1(3541.76,250) 3541.76,442.3 ; v1(3762.24,530.79) 3673.75,442.3 3541.76,442.3
  other v1: 2145.91,304.73 2145.91,351.73 2263.56,709.56
3P3V_RX: 3P3RX.1 R132.1 | length 105.4
  Top Layer L1 w25: 3P3RX.1@4558,515 R132.1@4663.44,515
3P3V_USB: C138.1 C210.1 FTDI_3P3V.3 L26.2 | length 146.8
  Bottom Layer - L10 w16.5: v1(83.74,839) 83.74,722.26 92.46,713.54 v1(110.24,713.54)
  other v1: 83.74,775.86
3P3VAUX: C143.1 FMC_RX1.D32 J1.4 U16.8 | length 1706.1
  Top Layer L1 w18: J1.4@3617,540 3699,622 C143.1@3739.14,622 U16.8@3739.14,690
  Signals - L8 w18: v1(3739.14,665) 3839.14,765 5109,765 v3(5134,740)
  Bottom Layer - L10 w18: v3(5134,740) FMC_RX1.D32@5159,765
5P0_12P0V_INT: C145.1 C146.1 C147.1 C167.1 C173.1 C184.1 C220.2 C221.2 C222.2 C223.2 C225.2 C226.2 C227.2 EXT5V_FMC12V.2 R70.1 R78.1 R79.2 R94.2 U7.8 U9.11 U9.12 U9.13 U9.14 | length 307.8
  Top Layer L1 w10: v1@3490.47,1396 U9.11@3490.47,1429.51 ; 3510.16,1396 U9.12@3510.16,1429.51 ; 3529.84,1396 U9.13@3529.84,1429.51 ; v1@3549.53,1396 U9.14@3549.53,1429.51
  Top Layer L1 w18: v1(3494.47,1340) v1(3545.53,1340)
  Bottom Layer - L10 w8: 3537.77,1403.76 v1(3545.53,1396)
  Bottom Layer - L10 w18: v1@4356,1289.56 4391.19,1254.37 R70.1@4391.19,1192.41
  other v1: 4411,235.85 3157.69,990 3072.69,1090 3771.31,1090 4238.69,1090 4279,1290 4315,1290 4356,1290 3520,1340 3494.47,1396 3520,1396 3544,1740 3072.69,1790 3771.31,1790 4026.69,1790 3114.68,2511.44
12P0V_RX: EXT5V_FMC12V.3 FMC_RX1.C35 FMC_RX1.C37 | length 176.8
  Bottom Layer - L10 w18: v1(5184,490) FMC_RX1.C37@5209,515 ; v3(5234,490) FMC_RX1.C37@5209,515 ; v3(5234,540) FMC_RX1.C37@5209,515 ; v3(5234,590) FMC_RX1.C35@5209,615 v3(5234,640)
CLK0_N: R63.1 U6.2 | length 101.6
  Top Layer L1 w8: U6.2@995.61,1973.77 995.61,1961.77 993.76,1959.93 993.76,1885.68 R63.1@1002.76,1876.68
CLK0_P: R64.1 U6.1 | length 101.6
  Top Layer L1 w8: R64.1@968.76,1876.68 977.76,1885.68 977.76,1959.93 975.92,1961.77 U6.1@975.92,1973.77
CLK3_N: R61.1 U6.14 | length 101.6
  Top Layer L1 w8: U6.14@1231.83,1973.77 1231.83,1961.77 1229.99,1959.93 1229.99,1885.68 R61.1@1238.98,1876.69
CLK3_P: R62.1 U6.13 | length 101.6
  Top Layer L1 w8: R62.1@1204.98,1876.69 1213.98,1885.68 1213.98,1959.93 1212.14,1961.77 U6.13@1212.14,1973.77
CLK4_N: R59.1 U6.25 | length 101.6
  Top Layer L1 w8: U6.25@1296.79,2156.84 1308.79,2156.84 1310.63,2155 1384.87,2155 R59.1@1393.87,2164
CLK4_P: R60.1 U6.24 | length 101.6
  Top Layer L1 w8: U6.24@1296.79,2137.16 1308.79,2137.16 1310.63,2139 1384.87,2139 R60.1@1393.87,2130
CLK11_N: R43.1 U6.57 | length 101.6
  Top Layer L1 w8: R43.1@853.24,2130 862.24,2139 936.49,2139 938.33,2137.16 U6.57@950.33,2137.16
CLK11_P: R44.1 U6.56 | length 101.6
  Top Layer L1 w8: R44.1@853.24,2164 862.24,2155 936.49,2155 938.33,2156.84 U6.56@950.33,2156.84
CLKIN1_N: C112.1 C123.1 U6.35 | length 101.6
  Top Layer L1 w8: v4(1224.67,2417.32) 1233.67,2408.32 1233.67,2334.07 1231.83,2332.23 U6.35@1231.83,2320.23
CLKIN1_P: C113.1 C114.2 U6.34 | length 101.6
  Top Layer L1 w8: U6.34@1251.51,2320.23 1251.51,2332.23 1249.67,2334.07 1249.67,2408.32 v4(1258.67,2417.32)
D0_N: C9.1 FMC_RX1.C6 | length 4238.1
  Signals - L8 w4: v1(1277.84,1695.8) 1287.34,1705.3 1287.34,1747.83 1408.5,1869 5051.69,1869 5055,1872.31 5055,2057.31 5066.69,2069 5163,2069 v3(5184,2090)
  Bottom Layer - L10 w8: v3(5184,2090) FMC_RX1.C6@5209,2065
D0_P: C7.1 FMC_RX1.C7 | length 4238.3
  Signals - L8 w4: v1(1304.84,1695.8) 1295.34,1705.3 1295.34,1744.52 1411.82,1861 5055,1861 5063,1869 5063,2054 5070,2061 5179,2061 5189,2051 5189,2045 v3(5184,2040)
  Bottom Layer - L10 w8: v3(5184,2040) FMC_RX1.C7@5209,2015
D1_N: C12.1 FMC_RX1.A2 | length 4380.6
  Signals - L8 w4: v1(1609.19,1501.14) 1618.69,1491.64 1650.31,1491.64 1727.68,1569 4901.69,1569 4905,1572.31 4905,1811 4913,1819 5101.69,1819 5105,1822.31 5105,1961 5113,1969 5198,1969 5205,1976 5205,2207.31 5216.69,2219 5263,2219 v3(5284,2240)
  Bottom Layer - L10 w8: v3(5284,2240) FMC_RX1.A2@5309,2265
D1_P: C10.1 FMC_RX1.A3 | length 4380.6
  Signals - L8 w4: v1(1609.19,1474.14) 1618.69,1483.64 1653.63,1483.64 1730.99,1561 4905,1561 4913,1569 4913,1807.69 4916.31,1811 5105,1811 5113,1819 5113,1957.69 5116.31,1961 5201.31,1961 5213,1972.69 5213,2204 5220,2211 5263,2211 v3(5284,2190)
  Bottom Layer - L10 w8: v3(5284,2190) FMC_RX1.A3@5309,2215
D2_N: C14.1 FMC_RX1.A6 | length 4374.4
  Signals - L8 w4: v1(1519.19,1442.08) 1528.69,1432.58 1650.31,1432.58 1736.73,1519 4951.69,1519 4955,1522.31 4955,1761 4963,1769 5151.69,1769 5155,1772.31 5155,1911 5163,1919 5248,1919 5255,1926 5255,2007.31 5266.69,2019 5313,2019 v3(5334,2040)
  Bottom Layer - L10 w8: FMC_RX1.A6@5309,2065 v3(5334,2040)
D2_P: C13.1 FMC_RX1.A7 | length 4374.4
  Signals - L8 w4: v1(1519.19,1415.08) 1528.69,1424.58 1653.63,1424.58 1740.05,1511 4955,1511 4963,1519 4963,1757.69 4966.31,1761 5155,1761 5163,1769 5163,1907.69 5166.31,1911 5251.31,1911 5263,1922.69 5263,2004 5270,2011 5313,2011 v3(5334,1990)
  Bottom Layer - L10 w8: FMC_RX1.A7@5309,2015 v3(5334,1990)
D3_N: C17.1 FMC_RX1.A10 | length 4149.1
  Signals - L8 w4: v1(1609.19,1383.03) 1618.69,1373.53 1650.31,1373.53 1745.79,1469 5001.69,1469 5005,1472.31 5005,1711 5013,1719 5201.69,1719 5205,1722.31 5205,1861 5213,1869 5263,1869 v3(5284,1890)
  Bottom Layer - L10 w8: v3(5284,1890) FMC_RX1.A10@5309,1865
D3_P: C15.1 FMC_RX1.A11 | length 4149.1
  Signals - L8 w4: v1(1609.19,1356.03) 1618.69,1365.53 1653.63,1365.53 1749.1,1461 5005,1461 5013,1469 5013,1707.69 5016.31,1711 5205,1711 5213,1719 5213,1857.69 5216.31,1861 5263,1861 v3(5284,1840)
  Bottom Layer - L10 w8: v3(5284,1840) FMC_RX1.A11@5309,1815
D4_N: C21.1 FMC_RX1.A14 | length 4128.8
  Signals - L8 w4: v1(1519.19,1323.97) 1528.69,1314.47 1650.31,1314.47 1704.84,1369 5051.69,1369 5055,1372.31 5055,1661 5063,1669 5263,1669 v3(5284,1690)
  Bottom Layer - L10 w8: v3(5284,1690) FMC_RX1.A14@5309,1665
D4_P: C20.1 FMC_RX1.A15 | length 4128.8
  Signals - L8 w4: v1(1519.19,1296.97) 1528.69,1306.47 1653.63,1306.47 1708.16,1361 5055,1361 5063,1369 5063,1657.69 5066.31,1661 5263,1661 v3(5284,1640)
  Bottom Layer - L10 w8: v3(5284,1640) FMC_RX1.A15@5309,1615
D5_N: C23.1 FMC_RX1.A18 | length 4231.6
  Signals - L8 w4: v1(1609.19,1264.92) 1618.69,1255.42 1650.31,1255.42 1713.9,1319 5101.69,1319 5105,1322.31 5105,1611 5113,1619 5251.31,1619 5263,1607.31 5263,1476 5270,1469 5313,1469 v3(5334,1490)
  Bottom Layer - L10 w8: FMC_RX1.A18@5309,1465 v3(5334,1490)
D5_P: C22.1 FMC_RX1.A19 | length 4231.6
  Signals - L8 w4: v1(1609.19,1237.92) 1618.69,1247.42 1653.63,1247.42 1717.21,1311 5105,1311 5113,1319 5113,1607.69 5116.31,1611 5248,1611 5255,1604 5255,1472.69 5266.69,1461 5313,1461 v3(5334,1440)
  Bottom Layer - L10 w8: FMC_RX1.A19@5309,1415 v3(5334,1440)
D6_N: C28.1 FMC_RX1.B16 | length 4086.3
  Signals - L8 w4: v1(1519.19,1205.86) 1528.69,1196.36 1650.31,1196.36 1722.95,1269 5151.69,1269 5155,1272.31 5155,1561 5163,1569 5213,1569 v3(5234,1590)
  Bottom Layer - L10 w8: v3(5234,1590) FMC_RX1.B16@5259,1565
D6_P: C26.1 FMC_RX1.B17 | length 4086.3
  Signals - L8 w4: v1(1519.19,1178.86) 1528.69,1188.36 1653.63,1188.36 1726.27,1261 5155,1261 5163,1269 5163,1557.69 5166.31,1561 5213,1561 v3(5234,1540)
  Bottom Layer - L10 w8: v3(5234,1540) FMC_RX1.B17@5259,1515
D7_N: C31.1 FMC_RX1.B12 | length 4717
  Signals - L8 w4: v1(1304.84,984.2) 1304.84,999.89 1316.15,1011.2 4960.86,1011.2 5363,1413.34 5363,1757.31 5351.31,1769 5305,1769 v3(5284,1790)
  Bottom Layer - L10 w8: FMC_RX1.B12@5259,1765 v3(5284,1790)
D7_P: C29.1 FMC_RX1.B13 | length 4716.9
  Signals - L8 w4: v1(1277.84,984.2) 1312.84,1019.2 4957.54,1019.2 5355,1416.66 5355,1754 5348,1761 5296,1761 5284,1749 v3(5284,1740)
  Bottom Layer - L10 w8: FMC_RX1.B13@5259,1715 v3(5284,1740)
DEVCLK_N: C33.1 C36.1 U2.16 | length 139.9
  Bottom Layer - L10 w8: v1(833.57,1481.45) 839.07,1475.95 968.63,1475.95 U2.16@970.47,1477.8
DEVCLK_P: C30.1 C32.1 U2.15 | length 139.9
  Bottom Layer - L10 w8: v1(833.57,1454.45) 839.07,1459.95 968.63,1459.95 U2.15@970.47,1458.11
DEVCLKARX_N: FMC_RX1.D5 R60.2 | length 3763.5
  Signals - L8 w4: v1(1433.24,2130) 1446.25,2143 1471.06,2143 1503.06,2111 5113,2111 v3(5134,2090)
  Bottom Layer - L10 w8: v3(5134,2090) FMC_RX1.D5@5159,2115
DEVCLKARX_P: FMC_RX1.D4 R59.2 | length 3763.4
  Signals - L8 w4: v1(1433.25,2164) 1446.24,2151 1474.37,2151 1506.38,2119 5113,2119 v3(5134,2140)
  Bottom Layer - L10 w8: v3(5134,2140) FMC_RX1.D4@5159,2165
DEVCLKBRX_N: FMC_RX1.G7 R63.2 | length 4159.7
  Signals - L8 w4: v1(1002.76,1837.31) 989.76,1850.32 989.76,1858.13 995.95,1864.32 1161.32,1864.32 1258,1961 4901.31,1961 4913,1972.69 4913,2004 4920,2011 4979,2011 4989,2001 4989,1995 v3(4984,1990)
  Bottom Layer - L10 w8: v3(4984,1990) FMC_RX1.G7@5009,2015
DEVCLKBRX_P: FMC_RX1.G6 R64.2 | length 4159.4
  Signals - L8 w4: v1(968.76,1837.32) 981.76,1850.32 981.76,1861.45 992.63,1872.32 1158,1872.32 1254.69,1969 4898,1969 4905,1976 4905,2007.31 4916.69,2019 4963,2019 v3(4984,2040)
  Bottom Layer - L10 w8: v3(4984,2040) FMC_RX1.G6@5009,2065
EE_ADDR0_RX: FMC_RX1.C34 U16.1 | length 1233.2
  Top Layer L1 w8: U16.1@4006.86,690 v1(4062.16,690)
  Signals - L3 w4: v1(4062.16,690) 4087.16,665 5159,665 v3(5184,690)
  Bottom Layer - L10 w8: v3(5184,690) FMC_RX1.C34@5209,665
EE_ADDR1_RX: FMC_RX1.D35 U16.2 | length 1325.6
  Top Layer L1 w8: U16.2@4006.86,740 v1(4062.16,740)
  Signals - L3 w4: v1(4062.16,740) 4087.17,715 5196,715 5209,702 5209,665 v3(5184,640)
  Bottom Layer - L10 w8: FMC_RX1.D35@5159,615 v3(5184,640)
FTDI_ADC_SCLK: R109.2 U12.14 | length 122.5
  Top Layer L1 w8: U12.14@3762.24,403.91 3831.85,403.91 3866.44,438.5 R109.2@3870.44,438.5
FTDI_ADC_SCSB: R118.2 R123.1 U12.11 | length 123
  Top Layer L1 w8: U12.11@3762.24,327.14 3812.94,327.14 R123.1@3822,318.09 3833.56,306.53 3855.41,306.53 R118.2@3870.44,291.5
FTDI_ADC_SDI: R111.2 U12.13 | length 112.8
  Top Layer L1 w8: U12.13@3762.24,378.32 3859.26,378.32 R111.2@3870.44,389.5
FTDI_ADC_SDO: R110.2 U12.12 | length 113.3
  Top Layer L1 w8: U12.12@3762.24,352.73 3858.21,352.73 R110.2@3870.44,340.5
FTDI_LMK_CSB: R68.2 R130.2 U13.40 | length 347.3
  Top Layer L1 w8: U13.40@2718.98,478.16 2785.45,478.16 v1(2790.45,483.16) ; v1(2935.88,440) R68.2@2960.88,440
  Signals - L6 w4: v1(2790.45,483.16) 2892.72,483.16 v1(2935.88,440)
  Bottom Layer - L10 w8: v1(2790.45,483.16) 2859.25,483.16 R130.2@2871,494.9
FTDI_LMX_LE: R113.2 R131.2 U13.41 | length 308.3
  Top Layer L1 w8: U13.41@2718.98,497.84 2773.45,497.84 v1(2778.44,502.84) ; v1(2936.44,540) R113.2@2961.44,540
  Signals - L6 w4: v1(2778.44,502.84) 2899.28,502.84 v1(2936.44,540)
  Bottom Layer - L10 w8: v1(2778.44,502.84) 2810.25,502.84 R131.2@2822,514.59
FTDI_LMX_LMK_CLK: R115.2 U13.38 | length 494.8
  Top Layer L1 w8: U13.38@2718.98,438.79 2773.45,438.79 v1(2778.44,433.79) ; R115.2@3008.32,157.56 v1(3008.32,198)
  Signals - L6 w4: v1(2778.44,433.79) 2767,422.34 2767,350 2820,297 2892,297 2945,244 2962.32,244 v1(3008.32,198)
FTDI_LMX_LMK_DATA: R114.2 U13.39 | length 314.3
  Top Layer L1 w8: U13.39@2718.98,458.47 2785.45,458.47 v1(2790.45,453.47) ; v1(2935.88,298) R114.2@2960.88,298
  Signals - L6 w4: v1(2790.45,453.47) 2935.88,308.04 v1(2935.88,298)
FTDI_LMX_R1: R143.2 U13.43 | length 1869.2
  Top Layer L1 w8: U13.43@2718.98,537.21 2754.21,537.21 2768,551 2768,649 3015,896 v1(3015,990)
  Signals - L3 w4: v1(2211.45,1740) 2228,1740 2250,1718 2250,1607 2315,1542 2417,1542 2491,1468 2491,1367 2693,1165 2724,1165 2899,990 v1(3015,990)
  Bottom Layer - L10 w18: R143.2@2176.7,1740 v1@2211.48,1740
FTDI_LMX_R2: R142.2 U13.44 | length 1799.4
  Top Layer L1 w8: U13.44@2718.98,556.9 2683.74,556.9 2642,598.64 2642,628 2745,731 2790,731 2981,922 v1(2981,940)
  Signals - L3 w4: v1(2156.37,1540) 2186.37,1510 2233,1510 2255,1488 2255,1402 2316,1341 2401,1341 2452,1290 2452,1224 2736,940 v1(2981,940)
  Bottom Layer - L10 w18: R142.2@2121.62,1540 v1(2156.37,1540)
FTDI_TS_SMBCLK: R125.2 U13.26 | length 552.5
  Top Layer L1 w8: v1(2523,189.03) 2530,196.03 U13.26@2530,269.5
  Bottom Layer - L10 w8: v1(2523,189.03) 2530,196.03 2530,245 2584,299 2746,299 2813.77,366.77 2854.8,366.77 v1(2879.56,342.01)
FTDI_TS_SMBDAT: R124.2 U13.28 | length 365.7
  Top Layer L1 w8: v1(2569.37,215.03) U13.28@2569.37,269.5
  Bottom Layer - L10 w8: v1(2569.37,215.03) 2623.34,269 2754.99,269 v1(2828,342.01)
